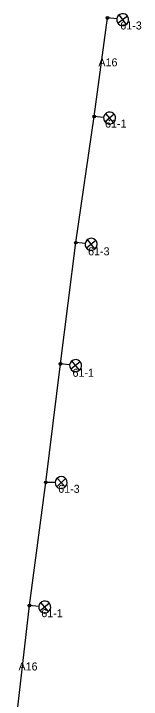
# Model space of a CAD drawing. Extents: x 25497851 to 25498523, y 6686544 to 6687372.
# Drawn here: x 25498446.6 to 25498494.4, y 6686878 to 6687134.9 of the extents above; entities that cross this region are included whole.
import ezdxf

# ---------------------------------------------------------------- set-up
doc = ezdxf.new("R2010")
doc.units = 0
for name, color, linetype in [('EL_CABLE_ILMA', 7, 'Continuous'), ('KEYGWT_ANNOTATION', 7, 'Continuous'), ('Taso 1', 7, 'Continuous')]:
    doc.layers.add(name, color=color, linetype=linetype)

msp = doc.modelspace()

# ---------------------------------------------------------------- linework, layer by layer
at = {"layer": 'EL_CABLE_ILMA'}
for points in [[(25498476.78, 6687096.38), (25498481.71, 6687133.42)], [(25498469.9, 6687049.15), (25498476.78, 6687096.38)], [(25498464.07, 6687003.69), (25498469.9, 6687049.15)], [(25498458.62, 6686959.31), (25498464.07, 6687003.69)], [(25498452.51, 6686913.14), (25498458.62, 6686959.31)], [(25498446.61, 6686862.01), (25498452.51, 6686913.14)]]:
    msp.add_lwpolyline(points, dxfattribs=at)
at = {"layer": 'Taso 1'}
for p, q in [((25498485.18, 6687132.98), (25498481.71, 6687133.42)), ((25498489.17, 6687134.06), (25498485.66, 6687131.34)), ((25498488.78, 6687130.95), (25498486.05, 6687134.46)), ((25498484.22, 6687097.25), (25498480.79, 6687094.42)), ((25498483.92, 6687094.12), (25498481.09, 6687097.55)), ((25498480.27, 6687096.05), (25498476.78, 6687096.38)), ((25498473.38, 6687048.77), (25498469.9, 6687049.15)), ((25498477.35, 6687049.91), (25498473.88, 6687047.13)), ((25498477, 6687046.79), (25498474.22, 6687050.26)), ((25498471.52, 6687004.44), (25498468.05, 6687001.67)), ((25498471.18, 6687001.32), (25498468.4, 6687004.79)), ((25498467.55, 6687003.3), (25498464.07, 6687003.69)), ((25498465.97, 6686960.77), (25498462.77, 6686957.68)), ((25498465.92, 6686957.63), (25498462.82, 6686960.82)), ((25498462.12, 6686959.26), (25498458.62, 6686959.31)), ((25498459.65, 6686910.88), (25498456.82, 6686914.31)), ((25498456, 6686912.81), (25498452.51, 6686913.14)), ((25498459.95, 6686914.01), (25498456.52, 6686911.18))]:
    msp.add_line(p, q, dxfattribs=at)
for points in [[(25498489.64, 6687132.42), (25498489.62, 6687133.12), (25498489.38, 6687133.78), (25498488.95, 6687134.34), (25498488.37, 6687134.74), (25498487.7, 6687134.93), (25498486.99, 6687134.91), (25498486.33, 6687134.67), (25498485.77, 6687134.24), (25498485.38, 6687133.66), (25498485.18, 6687132.98), (25498485.2, 6687132.28), (25498485.44, 6687131.62), (25498485.87, 6687131.06), (25498486.46, 6687130.66), (25498487.13, 6687130.47), (25498487.83, 6687130.49), (25498488.5, 6687130.73), (25498489.05, 6687131.16), (25498489.45, 6687131.74)], [(25498484.74, 6687095.62), (25498484.7, 6687096.33), (25498484.44, 6687096.98), (25498483.99, 6687097.52), (25498483.4, 6687097.9), (25498482.72, 6687098.07), (25498482.01, 6687098.03), (25498481.36, 6687097.77), (25498480.82, 6687097.32), (25498480.44, 6687096.73), (25498480.27, 6687096.05), (25498480.31, 6687095.34), (25498480.57, 6687094.69), (25498481.02, 6687094.15), (25498481.61, 6687093.77), (25498482.29, 6687093.59), (25498483, 6687093.64), (25498483.65, 6687093.9), (25498484.19, 6687094.35), (25498484.57, 6687094.94)], [(25498477.85, 6687048.27), (25498477.81, 6687048.98), (25498477.57, 6687049.64), (25498477.13, 6687050.19), (25498476.54, 6687050.57), (25498475.86, 6687050.76), (25498475.16, 6687050.72), (25498474.5, 6687050.48), (25498473.95, 6687050.04), (25498473.56, 6687049.45), (25498473.38, 6687048.77), (25498473.41, 6687048.07), (25498473.66, 6687047.41), (25498474.1, 6687046.86), (25498474.69, 6687046.47), (25498475.36, 6687046.29), (25498476.07, 6687046.32), (25498476.73, 6687046.57), (25498477.27, 6687047.01), (25498477.66, 6687047.6)], [(25498472.02, 6687002.81), (25498471.99, 6687003.51), (25498471.74, 6687004.17), (25498471.3, 6687004.72), (25498470.71, 6687005.11), (25498470.03, 6687005.29), (25498469.33, 6687005.26), (25498468.67, 6687005.01), (25498468.12, 6687004.57), (25498467.74, 6687003.98), (25498467.55, 6687003.3), (25498467.58, 6687002.6), (25498467.83, 6687001.94), (25498468.27, 6687001.39), (25498468.86, 6687001), (25498469.54, 6687000.82), (25498470.24, 6687000.85), (25498470.9, 6687001.1), (25498471.45, 6687001.54), (25498471.84, 6687002.13)], [(25498466.62, 6686959.19), (25498466.52, 6686959.88), (25498466.21, 6686960.52), (25498465.72, 6686961.02), (25498465.1, 6686961.35), (25498464.4, 6686961.47), (25498463.71, 6686961.37), (25498463.08, 6686961.06), (25498462.57, 6686960.57), (25498462.24, 6686959.95), (25498462.12, 6686959.26), (25498462.22, 6686958.56), (25498462.53, 6686957.93), (25498463.02, 6686957.42), (25498463.64, 6686957.09), (25498464.33, 6686956.97), (25498465.03, 6686957.07), (25498465.66, 6686957.38), (25498466.17, 6686957.87), (25498466.5, 6686958.49)], [(25498460.47, 6686912.38), (25498460.43, 6686913.09), (25498460.17, 6686913.74), (25498459.72, 6686914.28), (25498459.13, 6686914.66), (25498458.45, 6686914.83), (25498457.74, 6686914.79), (25498457.09, 6686914.53), (25498456.55, 6686914.08), (25498456.17, 6686913.49), (25498456, 6686912.81), (25498456.04, 6686912.1), (25498456.3, 6686911.45), (25498456.75, 6686910.91), (25498457.34, 6686910.53), (25498458.02, 6686910.35), (25498458.73, 6686910.4), (25498459.38, 6686910.66), (25498459.92, 6686911.11), (25498460.3, 6686911.7)]]:
    msp.add_lwpolyline(points, close=True, dxfattribs=at)
for centre in [(25498481.71, 6687133.42), (25498476.78, 6687096.38), (25498469.9, 6687049.15), (25498464.07, 6687003.69), (25498458.62, 6686959.31), (25498452.51, 6686913.14)]:
    msp.add_circle(centre, 0.5, dxfattribs=at)

# ---------------------------------------------------------------- texts
at = {"layer": 'KEYGWT_ANNOTATION'}
for s, p in [('61-3', (25498486.52, 6687129.02)), ('A16', (25498478.31, 6687115.2)), ('61-1', (25498480.81, 6687092.25)), ('61-3', (25498474.46, 6687044.4)), ('61-1', (25498468.62, 6686998.88)), ('61-3', (25498463.27, 6686955.39)), ('61-1', (25498456.94, 6686908.78)), ('A16', (25498448.4, 6686888.81))]:
    msp.add_text(s, height=3, dxfattribs=at).set_placement(p)

doc.saveas('drawing.dxf')
